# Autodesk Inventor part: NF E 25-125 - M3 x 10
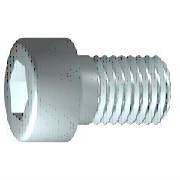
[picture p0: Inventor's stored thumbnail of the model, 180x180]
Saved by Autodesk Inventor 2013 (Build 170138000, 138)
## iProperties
IsCustomPart: 0
Created: 2007-03
Part Number: NF E 25-125 - M3 x 10
Material: Steel, Mild
Description: Slotted cheese head - Product grade A - Symbol C S
Document SubType Name: Modeling
Standard: NF E 25-125
Designer: Autodesk, Inc.
Standards Organization: AFNOR
Language: en-US
Size Designation: M3 x 10
Categories: <MemberInstance><Categories><Category DisplayName="Fasteners" InternalName="e4da775c-781d-43d5-af7c-5136215cf5a6" Mnemonic="FSTN"><Category DisplayName="Bolts"
Density: 7.86 g/cm^3
Mass: 1.04096 g
Surface Area: 2.01851 cm^2
Volume: 0.132438 cm^3
Author: Autodesk, Inc.
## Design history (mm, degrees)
sketch "Sketch1"
  geometry: L1 (-0.867, 0)-(10, 0); L2 (10, 0)-(10, 1.5); L3 (10, 1.5)-(1.25, 1.5); L4 (1.25, 1.5)-(0.943, 1.5); L5 (0.943, 1.5)-(0, 1.5); L6 (0, 1.5)-(0, 2.75); L7 (0, 2.75)-(-3, 2.75); L8 (-3, 2.75)-(-3, 1.443); L9 (-3, 1.443)-(-1.7, 1.443); L10 (-1.7, 1.443)-(-0.867, 0); L11 (-5.6, 0)-(12.6, 0) reference; L12 (0, -0.55)-(0, 3.3) reference; L13 (1.25, 1.5)-(0, 1.5)
  constraints: 22 end point, 6 parallel, 2 collinear, 2 perpendicular, 1 horizontal, 1 point on line
  dimensions: "d1" = 8.75 distance from line of L3.end L2 (= GEL); "d2" = 0.30683 distance of L4.end L3.end (computed from GAL); "d3" = 3 distance between parallel lines of L8 L6 (= KOH); "d4" = 1.3 distance of L8.end L9.end (= INTI); "d5" = 60 deg angle of L10 L1; "d6" = 3 diameter of L3 L1 (= GD); "d7" = 3 diameter of L5 L1 (= BDM); "d8" = 2.88675 diameter of L9 L1 (= 1.1547 x SW); "d9" = 5.5 diameter of L7 L1 (= KOD); "d26" = 10 distance between parallel lines of L12 L2 (= NLG)
revolve "Body" sketch "Sketch1" stored, may be unused: angle "d10" = 90 deg
sketch "Sketch2"
  geometry: L1 (0, -3.85)-(0, 3.85) reference; L2 (-3.85, 0)-(3.85, 0) reference; L3 (1.443, 0)-(0.722, -1.25); L4 (0.722, -1.25)-(-0.722, -1.25); L5 (-0.722, -1.25)-(-1.443, 0); L6 (-1.443, 0)-(-0.722, 1.25); L7 (-0.722, 1.25)-(0.722, 1.25); L8 (0.722, 1.25)-(1.443, 0); 2 further points
  constraints: 12 end point, 1 coincident, 1 horizontal alignment, 1 point on line, 12 other
extrude "Slot" join sketch "Sketch2" stored distance "d11" = 10; taper "d12" = 0 deg
workplane "Work Plane1"
fillet "Fillet2" dims "d30" = 0.1 (= R)
body "Solid1"
fillet "Fillet1" dims "d17" = 0.3 (= RR)
feature "Thread" dims "d13" = 8.75 (= GEL), "d14" = 0
chamfer "Chamfer1" distance "d15" = 0.30673 (= -0.5 x SPD + 0.5 x GD); stored, may be unused: second distance "d16" = 0.30673 (= GUL), angle "d27" = 45 deg
other parameters: "GD" = 3 (= NND) [user parameter; used in 2 equation terms], "NLG" = 10 [user parameter; used in 1 equation term], "GEL" = 8.75 [user parameter; used in 2 equation terms], "KOD" = 5.5 [user parameter; used in 1 equation term], "KOH" = 3 (= NND) [user parameter; used in 1 equation term], "INTI" = 1.3 [user parameter; used in 1 equation term], "GAL" = 0.30673 (= 0.61345 x PTC) [user parameter; used in 1 equation term], "GUL" = 0.30673 (= 0.61345 x PTC) [user parameter; used in 1 equation term], "BDM" = 3 (= NND) [user parameter; used in 1 equation term], "SW" = 2.5 [user parameter; used in 2 equation terms], "RR" = 0.3 [user parameter; used in 1 equation term], "SPD" = 2.38655 (= NND - 1.2269 x PTC) [user parameter; used in 1 equation term], "d19" = 0, "d28" = 0, "d29" = 0, "R" = 0.1 [user parameter; used in 1 equation term], "TOA" = 30 deg [user parameter], "GD1" = 2.38655 (= THREADDIA - 1.2269 x PTC) [user parameter], "THREADDIA" = 3 [user parameter; used in 1 equation term], "FAWI" = 45 deg [user parameter], "PTC" = 0.5 [user parameter; used in 5 equation terms], "NND" = 3 [user parameter; used in 4 equation terms], "E0" = 2.8875 (= 1.155 x SW) [user parameter]
